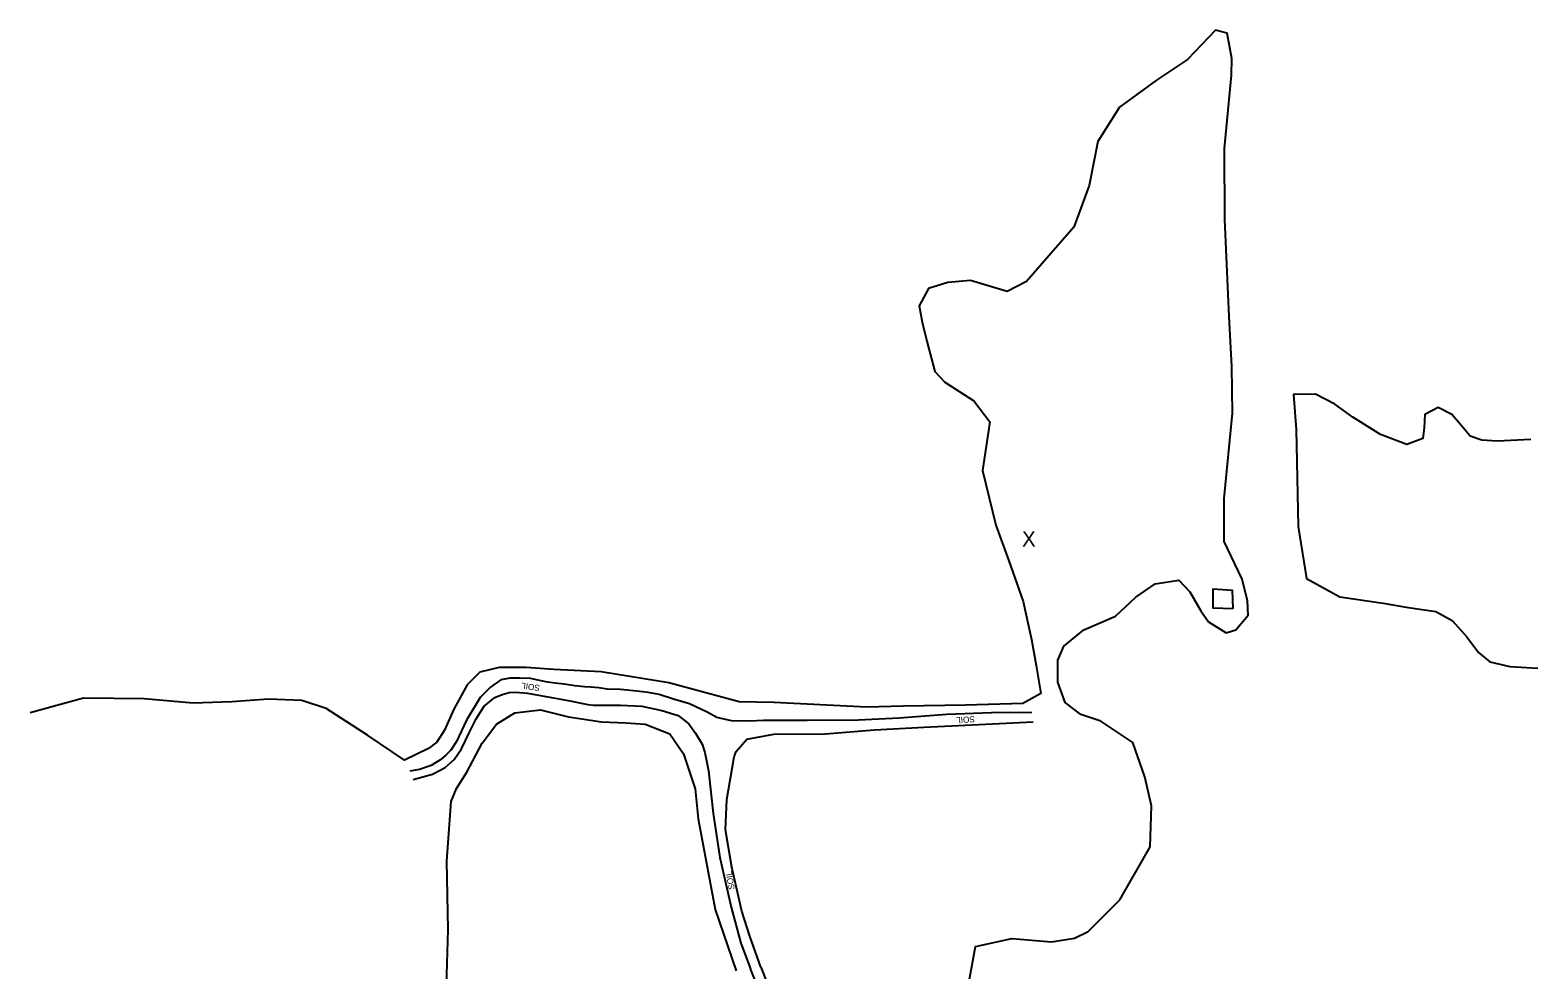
# Model space of a CAD drawing. Extents: x 2030130 to 2036320, y 723205 to 762423.
# Drawn here: x 2032803 to 2033791, y 742089 to 742704 of the extents above; entities that cross this region are included whole.
import ezdxf

# ---------------------------------------------------------------- set-up
doc = ezdxf.new("R2010")
doc.units = 0
for name, color, linetype in [('Draft_Station Labels Major', 7, 'Continuous'), ('Draft_Station Tics Major', 7, 'Continuous'), ('Exist Terrain Model Ground Surface', 7, 'Continuous'), ('Old_Level_23', 7, 'Continuous')]:
    doc.layers.add(name, color=color, linetype=linetype)

msp = doc.modelspace()

# ---------------------------------------------------------------- linework, layer by layer
at = {"layer": 'Draft_Station Labels Major'}
for points in [[(2033274.44, 742251.93), (2033262.31, 742252.16), (2033252.85, 742254.3), (2033246.35, 742257.81), (2033234.75, 742263.35), (2033224.27, 742266.38), (2033214.95, 742269.41), (2033207.75, 742270.78), (2033200.37, 742271.53), (2033189.73, 742272.69), (2033180.87, 742273), (2033175.53, 742273.72), (2033170.04, 742274.13), (2033166.03, 742274.4), (2033159.83, 742275.07), (2033152.69, 742276.06), (2033148.62, 742276.71), (2033141.89, 742277.58), (2033137.78, 742278.42), (2033130.76, 742279.91), (2033123.47, 742280.1), (2033117.38, 742280.11), (2033111.27, 742279.06), (2033104.46, 742274.3), (2033097.81, 742267.45), (2033088.87, 742252.56), (2033082.19, 742238.65), (2033078.45, 742232.88), (2033075.33, 742229.63), (2033071.27, 742226.32), (2033065.55, 742223.01), (2033058.08, 742220.37), (2033051.7, 742219.26)], [(2033053.81, 742213.73), (2033066.45, 742217.27), (2033074.77, 742221.7), (2033080.76, 742226.8), (2033085.44, 742233.79), (2033090.51, 742244.24), (2033095.23, 742253.53), (2033100.27, 742261.85), (2033107.4, 742267.35), (2033112.07, 742269.41), (2033116.68, 742270.69), (2033120.99, 742270.95), (2033128.73, 742270.36), (2033138.44, 742268.46), (2033145.7, 742267.29), (2033155.48, 742265.5), (2033168.23, 742262.77), (2033171.89, 742262.34), (2033189.76, 742262.43), (2033203.7, 742261.74), (2033216.66, 742258.95), (2033227.39, 742255.59), (2033234.43, 742250.13), (2033238.68, 742244), (2033243.1, 742236.84), (2033244.81, 742231.43), (2033246.56, 742222.73)], [(2033459.05, 742257.59), (2033432.68, 742257.49), (2033403.47, 742256.41), (2033372.28, 742253.92), (2033345.53, 742252.59), (2033312.01, 742252.41), (2033283.22, 742252.27), (2033274.44, 742251.93)], [(2033281.62, 742090.81), (2033274.42, 742111.22), (2033269.09, 742127.51), (2033262.56, 742156.36), (2033258.35, 742180.77), (2033259.37, 742200.58), (2033262.83, 742220.9), (2033264.1, 742228.66), (2033265.46, 742231.99), (2033272.35, 742240.24), (2033290.15, 742243.51), (2033323.99, 742243.55), (2033356.02, 742246.18), (2033388.57, 742248.03), (2033424.34, 742249.76), (2033460.01, 742251.48)], [(2033246.56, 742222.73), (2033247.23, 742219.37), (2033250.42, 742191.39), (2033254.62, 742162.63), (2033262.04, 742130.26), (2033268.47, 742106.52), (2033274.85, 742089.73)], [(2033279.47, 742078.56), (2033274.85, 742089.73)], [(2033281.62, 742090.81), (2033286.06, 742079.43)]]:
    msp.add_lwpolyline(points, dxfattribs=at)
at = {"layer": 'Draft_Station Tics Major'}
for points in [[(2033516.67, 742134.87), (2033536.56, 742169.6), (2033537.53, 742196.44), (2033533.06, 742215.57), (2033525.32, 742238), (2033504.18, 742251.93), (2033491.07, 742256.23), (2033480.81, 742264.12), (2033476.2, 742277.43), (2033476.21, 742291.92), (2033480.03, 742301.09), (2033493.06, 742311.84), (2033513.95, 742320.66), (2033527.24, 742333.2), (2033539.86, 742341.76), (2033555.47, 742344.26), (2033562.59, 742336.6), (2033569.77, 742324.12), (2033574.85, 742317.08), (2033586.35, 742309.79), (2033592.6, 742311.64), (2033600.78, 742321.36), (2033600.31, 742330.75), (2033596.91, 742344.85), (2033585.12, 742369.48), (2033585.08, 742397.68), (2033590.51, 742453.49), (2033590.05, 742484.14), (2033588.26, 742516.87), (2033585.42, 742580.33), (2033585.3, 742626.88), (2033589.77, 742674.8), (2033590.02, 742685.67), (2033586.95, 742702.33), (2033579.46, 742704.32), (2033560.95, 742685.09), (2033540.68, 742671.54), (2033516.46, 742654.02), (2033502.38, 742631.5), (2033496.73, 742602.7), (2033486.56, 742575.43), (2033471.73, 742558.38), (2033455.62, 742539.75), (2033442.83, 742533.29), (2033418.99, 742540.38), (2033404.13, 742539.17), (2033391.48, 742535.24), (2033385.31, 742523.94), (2033387.16, 742513.24), (2033390.3, 742500.65), (2033395.65, 742480.9), (2033402.07, 742473.89), (2033420.99, 742461.7), (2033431.68, 742447.9), (2033426.77, 742415.94), (2033435.46, 742380.15), (2033444.11, 742356.91), (2033453.35, 742330.29), (2033458.82, 742305.34), (2033461.95, 742288.3), (2033464.91, 742270.07), (2033453.08, 742263.58), (2033415.59, 742262.52), (2033374.74, 742261.84), (2033351.11, 742261.04), (2033290.09, 742264.22), (2033267.42, 742264.56), (2033221.39, 742277.09), (2033177.06, 742284.31), (2033145.9, 742285.69), (2033127.9, 742287.03), (2033110.12, 742287.05), (2033097.49, 742284.09), (2033089.27, 742275.72), (2033080.45, 742259.7), (2033074.3, 742246.08), (2033069.27, 742238.26), (2033063.82, 742234.03), (2033048.12, 742226.49), (2033023.85, 742242.78), (2032996.86, 742260.34), (2032980.9, 742265.5), (2032959.11, 742266.37), (2032935.08, 742264.54), (2032909.69, 742263.83), (2032877.72, 742266.62), (2032838.02, 742267.1), (2032802.99, 742257.38)], [(2033785.94, 742436.24), (2033764.1, 742435.17), (2033753.92, 742435.92), (2033746.15, 742438.45), (2033739.74, 742446.42), (2033734.23, 742452.62), (2033725.12, 742457.23), (2033716.45, 742452.64), (2033716, 742444.06), (2033715.1, 742436.95), (2033704.76, 742433.04), (2033687.38, 742439.7), (2033669.41, 742450.89), (2033657.5, 742459.46), (2033644.78, 742465.96), (2033630.51, 742465.81), (2033632.15, 742442.91), (2033633.46, 742379.37), (2033638.95, 742345.35), (2033660.74, 742333.27), (2033689.25, 742329.3), (2033704.2, 742326.67), (2033723.66, 742323.65), (2033734.33, 742317.77), (2033743.91, 742307.05), (2033751.67, 742296.8), (2033759.1, 742290.74), (2033772.17, 742287.78), (2033790.52, 742286.7)], [(2033075.01, 742056.26), (2033076.75, 742115.5), (2033075.96, 742160.38), (2033078.7, 742199.31), (2033082.25, 742207.84), (2033088.92, 742218.46), (2033099.14, 742237.62), (2033108.39, 742250.04), (2033120.46, 742257.34), (2033137.29, 742259.47), (2033155.7, 742254.73), (2033177.31, 742251.51), (2033193.06, 742250.94), (2033205.78, 742250.05), (2033221.97, 742243.57), (2033230.96, 742230.63), (2033238.61, 742207.6), (2033240.64, 742188.05), (2033251.66, 742128.7), (2033265.36, 742088.56)], [(2033411.77, 742047.11), (2033422.09, 742104.48), (2033446.08, 742109.72), (2033471.97, 742107.56), (2033487.04, 742109.88), (2033495.88, 742114.29), (2033516.67, 742134.87)]]:
    msp.add_lwpolyline(points, dxfattribs=at)
at = {"layer": 'Exist Terrain Model Ground Surface'}
msp.add_lwpolyline([(2033590.74, 742325.4), (2033577.88, 742325.98), (2033577.82, 742338.63), (2033590.34, 742337.8)], close=True, dxfattribs=at)

# ---------------------------------------------------------------- texts
at = {"layer": 'Draft_Station Tics Major'}
msp.add_text('X', height=10, dxfattribs=at).set_placement((2033452.68, 742366.23))
at = {"layer": 'Old_Level_23'}
for rotation, p in [(172.00548, (2033137.03, 742275.53)), (183.21484, (2033421.61, 742255.25)), (100.00016, (2033264.53, 742142.05))]:
    msp.add_text('SOIL', height=4, rotation=rotation, dxfattribs=at).set_placement(p)

doc.saveas('drawing.dxf')
